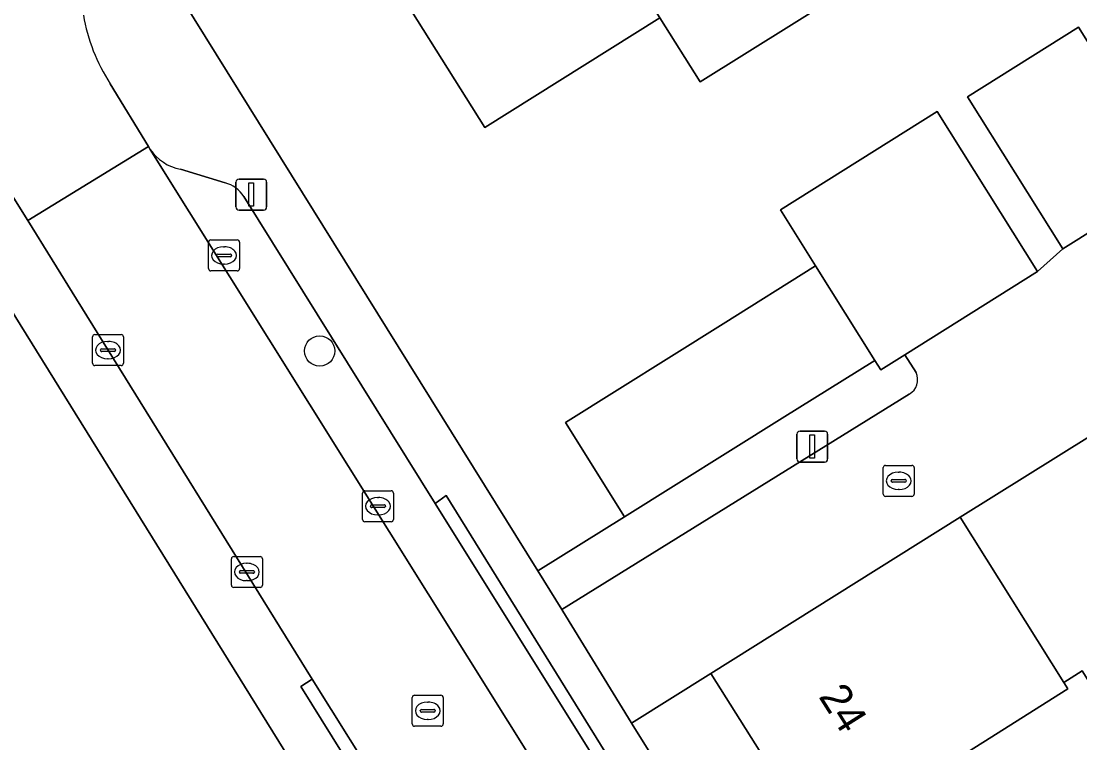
# Model space of a CAD drawing. Extents: x 159352 to 160617, y 385888 to 387323.
# Drawn here: x 159852.67 to 159886.84, y 386123.6 to 386146.89 of the extents above; entities that cross this region are included whole.
import ezdxf

# ---------------------------------------------------------------- set-up
doc = ezdxf.new("R2010")
doc.units = 0
for name, color, linetype in [('IMGEO_Boom', 7, 'Continuous'), ('IMGEO_Erf', 7, 'Continuous'), ('IMGEO_Kolk', 7, 'Continuous'), ('IMGEO_Lichtmast', 7, 'Continuous'), ('IMGEO_Pand', 7, 'Continuous'), ('IMGEO_Pand_nummerreeks', 7, 'Continuous'), ('IMGEO_Parkeervlak_open', 7, 'Continuous'), ('IMGEO_Rijbaan_lokaal_open', 7, 'Continuous'), ('IMGEO_Rioolput', 7, 'Continuous'), ('IMGEO_Voetpad_open', 7, 'Continuous')]:
    doc.layers.add(name, color=color, linetype=linetype)

msp = doc.modelspace()

# ---------------------------------------------------------------- linework, layer by layer
at = {"layer": 'IMGEO_Boom'}
msp.add_circle((159862.302, 386136.247), 0.489, dxfattribs=at)
at = {"layer": 'IMGEO_Erf'}
for points in [[(159898.899, 386175.898), (159898.457, 386176.619), (159857.761, 386151.157), (159857.246, 386148.607), (159869.341, 386129.146), (159872.146, 386130.889), (159870.235, 386133.94), (159875.321, 386137.125), (159878.306, 386138.994), (159877.173, 386140.803), (159882.231, 386143.974), (159885.469, 386138.81), (159886.292, 386139.546), (159883.214, 386144.455), (159886.794, 386146.7), (159888.431, 386144.089), (159890.606, 386145.45), (159893.514, 386147.27), (159891.873, 386149.892), (159894.719, 386151.673)], [(159910.666, 386138.39), (159909.392, 386137.597), (159905.803, 386135.363), (159902.311, 386140.975), (159905.904, 386143.202), (159905.861, 386143.271), (159905.944, 386143.322), (159907.128, 386144.061), (159906.28, 386145.421), (159882.976, 386130.886), (159886.323, 386125.546), (159886.916, 386125.918), (159890.389, 386120.378)], [(159848.306, 386127.223), (159852.925, 386119.851), (159856.453, 386122.037), (159858.392, 386118.99), (159858.735, 386118.451), (159862.703, 386120.84), (159862.373, 386121.402), (159848.413, 386143.9)]]:
    msp.add_lwpolyline(points, dxfattribs=at)
for points in [[(159879.59, 386150.235), (159880.565, 386148.68), (159874.585, 386144.932), (159873.286, 386147.004), (159867.629, 386143.458), (159864.075, 386149.131), (159869.73, 386152.674), (159875.711, 386156.422), (159881.466, 386160.028), (159887.22, 386163.634), (159892.974, 386167.239), (159898.855, 386170.924), (159900.178, 386168.813), (159903.127, 386170.661), (159906.377, 386165.476), (159903.259, 386163.522), (159902.564, 386164.631), (159899.832, 386162.919), (159901.572, 386160.144), (159898.594, 386158.278), (159899.279, 386157.186), (159893.523, 386153.579), (159891.099, 386157.447), (159885.345, 386153.841)], [(159895.244, 386093.428), (159894.652, 386093.066), (159891.078, 386098.783), (159892.253, 386099.525), (159889.031, 386104.628), (159885.668, 386109.955), (159882.395, 386115.14), (159881.261, 386114.429), (159877.686, 386120.134), (159878.28, 386120.505), (159874.93, 386125.838), (159872.371, 386124.236), (159899.841, 386080.344), (159902.814, 386075.83), (159904.679, 386077.058), (159901.105, 386082.758), (159901.707, 386083.135), (159898.498, 386088.246)]]:
    msp.add_lwpolyline(points, close=True, dxfattribs=at)
at = {"layer": 'IMGEO_Kolk'}
for p, q in [((159858.715, 386138.905), (159858.715, 386139.757)), ((159858.79, 386139.831), (159859.642, 386139.831)), ((159859.716, 386139.757), (159859.716, 386138.905)), ((159859.203, 386139.611), (159859.228, 386139.611)), ((159858.974, 386139.325), (159858.974, 386139.337)), ((159859.412, 386139.288), (159859.014, 386139.288)), ((159859.017, 386139.374), (159859.415, 386139.374)), ((159859.458, 386139.337), (159859.458, 386139.325)), ((159859.642, 386138.831), (159858.79, 386138.831)), ((159859.226, 386139.051), (159859.201, 386139.051)), ((159854.971, 386135.85), (159854.971, 386136.702)), ((159855.046, 386136.776), (159855.898, 386136.776)), ((159855.972, 386136.702), (159855.972, 386135.85)), ((159855.459, 386136.556), (159855.484, 386136.556)), ((159855.23, 386136.27), (159855.23, 386136.282)), ((159855.668, 386136.233), (159855.27, 386136.233)), ((159855.273, 386136.319), (159855.671, 386136.319)), ((159855.482, 386135.996), (159855.457, 386135.996)), ((159855.714, 386136.282), (159855.714, 386136.27)), ((159855.898, 386135.776), (159855.046, 386135.776)), ((159880.49, 386131.628), (159880.49, 386132.48)), ((159880.565, 386132.554), (159881.417, 386132.554)), ((159880.978, 386132.334), (159881.003, 386132.334)), ((159881.491, 386132.48), (159881.491, 386131.628)), ((159880.749, 386132.048), (159880.749, 386132.06)), ((159881.187, 386132.011), (159880.789, 386132.011)), ((159880.792, 386132.097), (159881.19, 386132.097)), ((159881.233, 386132.06), (159881.233, 386132.048)), ((159863.684, 386130.809), (159863.684, 386131.661)), ((159863.759, 386131.735), (159864.611, 386131.735)), ((159864.685, 386131.661), (159864.685, 386130.809)), ((159881.417, 386131.554), (159880.565, 386131.554)), ((159881.001, 386131.774), (159880.976, 386131.774)), ((159863.943, 386131.229), (159863.943, 386131.241)), ((159863.986, 386131.278), (159864.384, 386131.278)), ((159864.172, 386131.515), (159864.197, 386131.515)), ((159864.427, 386131.241), (159864.427, 386131.229)), ((159864.381, 386131.192), (159863.983, 386131.192)), ((159864.195, 386130.955), (159864.17, 386130.955)), ((159864.611, 386130.735), (159863.759, 386130.735)), ((159859.453, 386128.686), (159859.453, 386129.538)), ((159859.528, 386129.612), (159860.38, 386129.612)), ((159860.454, 386129.538), (159860.454, 386128.686)), ((159859.755, 386129.155), (159860.153, 386129.155)), ((159859.941, 386129.392), (159859.966, 386129.392)), ((159859.712, 386129.106), (159859.712, 386129.118)), ((159860.15, 386129.069), (159859.752, 386129.069)), ((159859.964, 386128.832), (159859.939, 386128.832)), ((159860.196, 386129.118), (159860.196, 386129.106)), ((159860.38, 386128.612), (159859.528, 386128.612))]:
    msp.add_line(p, q, dxfattribs=at)
for points in [[(159858.715, 386138.905), (159858.715, 386139.757)], [(159858.79, 386139.831), (159859.642, 386139.831)], [(159859.716, 386139.757), (159859.716, 386138.905)], [(159859.642, 386138.831), (159858.79, 386138.831)], [(159854.971, 386135.85), (159854.971, 386136.702)], [(159855.046, 386136.776), (159855.898, 386136.776)], [(159855.972, 386136.702), (159855.972, 386135.85)], [(159855.898, 386135.776), (159855.046, 386135.776)], [(159880.49, 386131.628), (159880.49, 386132.48)], [(159880.565, 386132.554), (159881.417, 386132.554)], [(159881.491, 386132.48), (159881.491, 386131.628)], [(159863.684, 386130.809), (159863.684, 386131.661)], [(159863.759, 386131.735), (159864.611, 386131.735)], [(159864.685, 386131.661), (159864.685, 386130.809)], [(159881.417, 386131.554), (159880.565, 386131.554)], [(159864.611, 386130.735), (159863.759, 386130.735)], [(159859.453, 386128.686), (159859.453, 386129.538)], [(159859.528, 386129.612), (159860.38, 386129.612)], [(159860.454, 386129.538), (159860.454, 386128.686)], [(159860.38, 386128.612), (159859.528, 386128.612)]]:
    msp.add_lwpolyline(points, dxfattribs=at)
for centre, radius, start, end in [((159858.792, 386139.755), 0.0765, 91.552, 178.448), ((159858.792, 386139.755), 0.0765, 91.552, 178.448), ((159859.64, 386139.755), 0.0765, 1.552, 88.448), ((159859.64, 386139.755), 0.0765, 1.552, 88.448), ((159859.014, 386139.334), 0.0403, 85.8775, 175.7526), ((159859.011, 386139.324), 0.0366, 178.938, 274.7102), ((159859.415, 386139.331), 0.043, 264.8664, 352.4533), ((159859.419, 386139.336), 0.0386, 1.7309, 96.639), ((159858.792, 386138.907), 0.0765, 181.552, 268.448), ((159858.792, 386138.907), 0.0765, 181.552, 268.448), ((159859.64, 386138.907), 0.0765, 271.552, 358.448), ((159859.64, 386138.907), 0.0765, 271.552, 358.448), ((159855.048, 386136.7), 0.0765, 91.552, 178.448), ((159855.048, 386136.7), 0.0765, 91.552, 178.448), ((159855.896, 386136.7), 0.0765, 1.552, 88.448), ((159855.896, 386136.7), 0.0765, 1.552, 88.448), ((159855.27, 386136.279), 0.0403, 85.8775, 175.7526), ((159855.267, 386136.269), 0.0366, 178.938, 274.7102), ((159855.671, 386136.276), 0.043, 264.8664, 352.4533), ((159855.675, 386136.281), 0.0386, 1.7309, 96.639), ((159855.048, 386135.852), 0.0765, 181.552, 268.448), ((159855.048, 386135.852), 0.0765, 181.552, 268.448), ((159855.896, 386135.852), 0.0765, 271.552, 358.448), ((159855.896, 386135.852), 0.0765, 271.552, 358.448), ((159880.567, 386132.478), 0.0765, 91.552, 178.448), ((159880.567, 386132.478), 0.0765, 91.552, 178.448), ((159881.415, 386132.478), 0.0765, 1.552, 88.448), ((159881.415, 386132.478), 0.0765, 1.552, 88.448), ((159880.789, 386132.057), 0.0403, 85.8775, 175.7526), ((159880.786, 386132.047), 0.0366, 178.938, 274.7102), ((159881.19, 386132.054), 0.043, 264.8664, 352.4533), ((159881.194, 386132.059), 0.0386, 1.7309, 96.639), ((159863.761, 386131.659), 0.0765, 91.552, 178.448), ((159863.761, 386131.659), 0.0765, 91.552, 178.448), ((159864.609, 386131.659), 0.0765, 1.552, 88.448), ((159864.609, 386131.659), 0.0765, 1.552, 88.448), ((159880.567, 386131.63), 0.0765, 181.552, 268.448), ((159880.567, 386131.63), 0.0765, 181.552, 268.448), ((159881.415, 386131.63), 0.0765, 271.552, 358.448), ((159881.415, 386131.63), 0.0765, 271.552, 358.448), ((159863.983, 386131.238), 0.0403, 85.8775, 175.7526), ((159863.98, 386131.228), 0.0366, 178.938, 274.7102), ((159864.384, 386131.235), 0.043, 264.8664, 352.4533), ((159864.388, 386131.24), 0.0386, 1.7309, 96.639), ((159863.761, 386130.811), 0.0765, 181.552, 268.448), ((159863.761, 386130.811), 0.0765, 181.552, 268.448), ((159864.609, 386130.811), 0.0765, 271.552, 358.448), ((159864.609, 386130.811), 0.0765, 271.552, 358.448), ((159859.53, 386129.536), 0.0765, 91.552, 178.448), ((159859.53, 386129.536), 0.0765, 91.552, 178.448), ((159860.378, 386129.536), 0.0765, 1.552, 88.448), ((159860.378, 386129.536), 0.0765, 1.552, 88.448), ((159859.752, 386129.115), 0.0403, 85.8775, 175.7526), ((159860.157, 386129.117), 0.0386, 1.7309, 96.639), ((159859.749, 386129.105), 0.0366, 178.938, 274.7102), ((159860.153, 386129.112), 0.043, 264.8664, 352.4533), ((159859.53, 386128.688), 0.0765, 181.552, 268.448), ((159859.53, 386128.688), 0.0765, 181.552, 268.448), ((159860.378, 386128.688), 0.0765, 271.552, 358.448), ((159860.378, 386128.688), 0.0765, 271.552, 358.448)]:
    msp.add_arc(centre, radius, start, end, dxfattribs=at)
for centre, major_axis, ratio, start_param, end_param in [((159859.202, 386139.331), (-0.387, 0.002), 0.722429, 4.712389, 7.853982), ((159859.227, 386139.331), (-0.39, 0.002), 0.717154, 1.570796, 4.712389), ((159855.458, 386136.276), (-0.387, 0.002), 0.722429, 4.712389, 7.853982), ((159855.483, 386136.276), (-0.39, 0.002), 0.717154, 1.570796, 4.712389), ((159880.977, 386132.054), (-0.387, 0.002), 0.722429, 4.712389, 7.853982), ((159881.002, 386132.054), (-0.39, 0.002), 0.717154, 1.570796, 4.712389), ((159864.171, 386131.235), (-0.387, 0.002), 0.722429, 4.712389, 7.853982), ((159864.196, 386131.235), (-0.39, 0.002), 0.717154, 1.570796, 4.712389), ((159859.94, 386129.112), (-0.387, 0.002), 0.722429, 4.712389, 7.853982), ((159859.965, 386129.112), (-0.39, 0.002), 0.717154, 1.570796, 4.712389)]:
    msp.add_ellipse(centre, major_axis=major_axis, ratio=ratio, start_param=start_param, end_param=end_param, dxfattribs=at)
at = {"layer": 'IMGEO_Lichtmast'}
for p, q in [((159859.702, 386141.795), (159860.492, 386141.795)), ((159860.492, 386141.795), (159859.702, 386141.795)), ((159859.602, 386140.895), (159859.602, 386141.695)), ((159859.602, 386141.695), (159859.602, 386140.895)), ((159860.592, 386141.695), (159860.592, 386140.895)), ((159860.592, 386140.895), (159860.592, 386141.695)), ((159860.492, 386140.795), (159859.702, 386140.795)), ((159859.702, 386140.795), (159860.492, 386140.795)), ((159877.806, 386133.66), (159878.596, 386133.66)), ((159878.596, 386133.66), (159877.806, 386133.66)), ((159877.706, 386132.76), (159877.706, 386133.56)), ((159877.706, 386133.56), (159877.706, 386132.76)), ((159878.696, 386133.56), (159878.696, 386132.76)), ((159878.696, 386132.76), (159878.696, 386133.56)), ((159878.596, 386132.66), (159877.806, 386132.66)), ((159877.806, 386132.66), (159878.596, 386132.66))]:
    msp.add_line(p, q, dxfattribs=at)
for points in [[(159860.022, 386141.67), (159860.172, 386141.67), (159860.172, 386140.92), (159860.022, 386140.92), (159860.022, 386141.67)], [(159878.126, 386133.535), (159878.276, 386133.535), (159878.276, 386132.785), (159878.126, 386132.785), (159878.126, 386133.535)]]:
    msp.add_lwpolyline(points, dxfattribs=at)
for centre, start, end in [((159859.702, 386141.695), 90, 180), ((159859.702, 386141.695), 90, 180), ((159860.492, 386141.695), 0, 90), ((159860.492, 386141.695), 360, 90), ((159859.702, 386140.895), 180, 270), ((159859.702, 386140.895), 180, 270), ((159860.492, 386140.895), 270, 0), ((159860.492, 386140.895), 270, 0), ((159877.806, 386133.56), 90, 180), ((159877.806, 386133.56), 90, 180), ((159878.596, 386133.56), 0, 90), ((159878.596, 386133.56), 360, 90), ((159877.806, 386132.76), 180, 270), ((159877.806, 386132.76), 180, 270), ((159878.596, 386132.76), 270, 0), ((159878.596, 386132.76), 270, 0)]:
    msp.add_arc(centre, 0.1, start, end, dxfattribs=at)
at = {"layer": 'IMGEO_Pand'}
for points in [[(159875.711, 386156.422), (159869.73, 386152.674), (159873.286, 386147.004), (159874.585, 386144.932), (159880.565, 386148.68), (159879.59, 386150.235)], [(159869.73, 386152.674), (159864.075, 386149.131), (159867.629, 386143.458), (159873.286, 386147.004)], [(159890.606, 386145.45), (159888.431, 386144.089), (159886.794, 386146.7), (159883.214, 386144.455), (159886.292, 386139.546), (159892.047, 386143.151)], [(159882.231, 386143.974), (159877.173, 386140.803), (159878.306, 386138.994), (159880.219, 386135.944), (159880.41, 386135.639), (159881.188, 386136.126), (159885.469, 386138.81)], [(159878.306, 386138.994), (159875.321, 386137.125), (159870.235, 386133.94), (159872.146, 386130.889), (159877.232, 386134.074), (159880.219, 386135.944)], [(159882.976, 386130.886), (159874.93, 386125.838), (159878.28, 386120.505), (159878.424, 386120.275), (159886.451, 386125.343), (159886.323, 386125.546)], [(159890.389, 386120.378), (159886.916, 386125.918), (159886.323, 386125.546), (159886.451, 386125.343), (159878.424, 386120.275), (159878.28, 386120.505), (159877.686, 386120.134), (159881.261, 386114.429), (159882.395, 386115.14), (159882.308, 386115.277)]]:
    msp.add_lwpolyline(points, close=True, dxfattribs=at)
at = {"layer": 'IMGEO_Parkeervlak_open'}
for points in [[(159856.835, 386142.755), (159877.345, 386109.956)], [(159859.248, 386141.671), (159857.807, 386142.111)], [(159866.027, 386131.328), (159859.854, 386141.231)], [(159871.362, 386122.775), (159866.027, 386131.328)]]:
    msp.add_lwpolyline(points, dxfattribs=at)
for centre, radius, start, end in [((159858.103, 386143.613), 1.531, 214.0845, 258.8624), ((159859.036, 386140.742), 0.953, 30.892, 77.1433)]:
    msp.add_arc(centre, radius, start, end, dxfattribs=at)
at = {"layer": 'IMGEO_Rijbaan_lokaal_open'}
for points in [[(159906.28, 386145.421), (159905.588, 386146.53), (159904.513, 386148.252), (159902.313, 386146.942), (159901.128, 386148.835), (159897.803, 386146.754), (159892.047, 386143.151), (159886.292, 386139.546), (159885.469, 386138.81), (159881.188, 386136.126), (159881.549, 386135.549)], [(159881.331, 386134.855), (159870.116, 386127.9), (159870.151, 386127.843), (159872.357, 386124.258), (159872.371, 386124.236), (159874.93, 386125.838), (159882.976, 386130.886), (159906.28, 386145.421)], [(159850.973, 386143.505), (159852.881, 386140.456), (159856.775, 386142.851), (159855.542, 386144.875)]]:
    msp.add_lwpolyline(points, dxfattribs=at)
msp.add_lwpolyline([(159872.955, 386108.168), (159873.411, 386107.439), (159877.345, 386109.956), (159856.835, 386142.755), (159856.775, 386142.851), (159852.881, 386140.456), (159854.453, 386137.92), (159862.065, 386125.649), (159864.459, 386121.826), (159866.743, 386118.245), (159866.899, 386117.869)], close=True, dxfattribs=at)
for centre, radius, start, end in [((159860.426, 386148.052), 5.826, 189.5354, 213.0456), ((159881.076, 386135.316), 0.527, 298.9037, 26.2191)]:
    msp.add_arc(centre, radius, start, end, dxfattribs=at)
at = {"layer": 'IMGEO_Rioolput'}
for p, q in [((159865.291, 386124.205), (159865.291, 386125.057)), ((159865.366, 386125.131), (159866.218, 386125.131)), ((159866.292, 386125.057), (159866.292, 386124.205)), ((159865.779, 386124.911), (159865.804, 386124.911)), ((159865.55, 386124.625), (159865.55, 386124.637)), ((159865.988, 386124.588), (159865.59, 386124.588)), ((159865.593, 386124.674), (159865.991, 386124.674)), ((159866.034, 386124.637), (159866.034, 386124.625)), ((159866.218, 386124.131), (159865.366, 386124.131)), ((159865.802, 386124.351), (159865.777, 386124.351))]:
    msp.add_line(p, q, dxfattribs=at)
for points in [[(159865.291, 386124.205), (159865.291, 386125.057)], [(159865.366, 386125.131), (159866.218, 386125.131)], [(159866.292, 386125.057), (159866.292, 386124.205)], [(159866.218, 386124.131), (159865.366, 386124.131)]]:
    msp.add_lwpolyline(points, dxfattribs=at)
for centre, radius, start, end in [((159865.368, 386125.055), 0.0765, 91.552, 178.448), ((159865.368, 386125.055), 0.0765, 91.552, 178.448), ((159866.216, 386125.055), 0.0765, 1.552, 88.448), ((159866.216, 386125.055), 0.0765, 1.552, 88.448), ((159865.59, 386124.634), 0.0403, 85.8775, 175.7526), ((159865.587, 386124.624), 0.0366, 178.938, 274.7102), ((159865.991, 386124.631), 0.043, 264.8664, 352.4533), ((159865.995, 386124.636), 0.0386, 1.7309, 96.639), ((159865.368, 386124.207), 0.0765, 181.552, 268.448), ((159865.368, 386124.207), 0.0765, 181.552, 268.448), ((159866.216, 386124.207), 0.0765, 271.552, 358.448), ((159866.216, 386124.207), 0.0765, 271.552, 358.448)]:
    msp.add_arc(centre, radius, start, end, dxfattribs=at)
for centre, major_axis, ratio, start_param, end_param in [((159865.778, 386124.631), (-0.387, 0.002), 0.722429, 4.712389, 7.853982), ((159865.803, 386124.631), (-0.39, 0.002), 0.717154, 1.570796, 4.712389)]:
    msp.add_ellipse(centre, major_axis=major_axis, ratio=ratio, start_param=start_param, end_param=end_param, dxfattribs=at)
at = {"layer": 'IMGEO_Voetpad_open'}
for points in [[(159912.742, 386053.291), (159913.077, 386052.786), (159913.468, 386052.304), (159913.581, 386051.533), (159916.785, 386053.532), (159903.963, 386074.085), (159902.814, 386075.83), (159899.841, 386080.344), (159872.371, 386124.236), (159872.357, 386124.258), (159870.151, 386127.843), (159870.116, 386127.9), (159869.341, 386129.146), (159857.246, 386148.607)], [(159848.806, 386145.565), (159846.595, 386144.231), (159848.413, 386143.9), (159862.373, 386121.402), (159862.703, 386120.84), (159863.515, 386119.625), (159862.072, 386118.665), (159867.01, 386110.716), (159869.269, 386107.089), (159872.236, 386102.341), (159873.056, 386100.938), (159873.777, 386100.186)], [(159855.542, 386144.875), (159856.775, 386142.851), (159856.835, 386142.755)], [(159861.692, 386125.414), (159862.065, 386125.649), (159854.453, 386137.92), (159852.881, 386140.456), (159850.973, 386143.505)], [(159857.807, 386142.111), (159859.248, 386141.671)], [(159859.854, 386141.231), (159866.027, 386131.328), (159866.387, 386131.585), (159871.698, 386123), (159871.362, 386122.775), (159912.738, 386056.579)], [(159881.549, 386135.549), (159881.188, 386136.126), (159880.41, 386135.639), (159880.219, 386135.944), (159877.232, 386134.074), (159872.146, 386130.889), (159869.341, 386129.146), (159870.116, 386127.9), (159881.331, 386134.855)], [(159866.899, 386117.869), (159866.743, 386118.245), (159864.459, 386121.826), (159864.07, 386121.6), (159861.692, 386125.414)]]:
    msp.add_lwpolyline(points, dxfattribs=at)
for points in [[(159871.362, 386122.775), (159871.698, 386123), (159866.387, 386131.585), (159866.027, 386131.328)], [(159862.065, 386125.649), (159861.692, 386125.414), (159864.07, 386121.6), (159864.459, 386121.826)]]:
    msp.add_lwpolyline(points, close=True, dxfattribs=at)
for centre, radius, start, end in [((159860.426, 386148.052), 5.826, 189.5354, 213.0456), ((159858.103, 386143.613), 1.531, 214.0845, 258.8624), ((159859.036, 386140.742), 0.953, 30.892, 77.1433), ((159881.076, 386135.316), 0.527, 298.9037, 26.2191)]:
    msp.add_arc(centre, radius, start, end, dxfattribs=at)

# ---------------------------------------------------------------- texts
at = {"layer": 'IMGEO_Pand_nummerreeks'}
msp.add_text('24', height=1, rotation=302.3846, dxfattribs=at).set_placement((159878.386, 386125.093))

doc.saveas('drawing.dxf')
